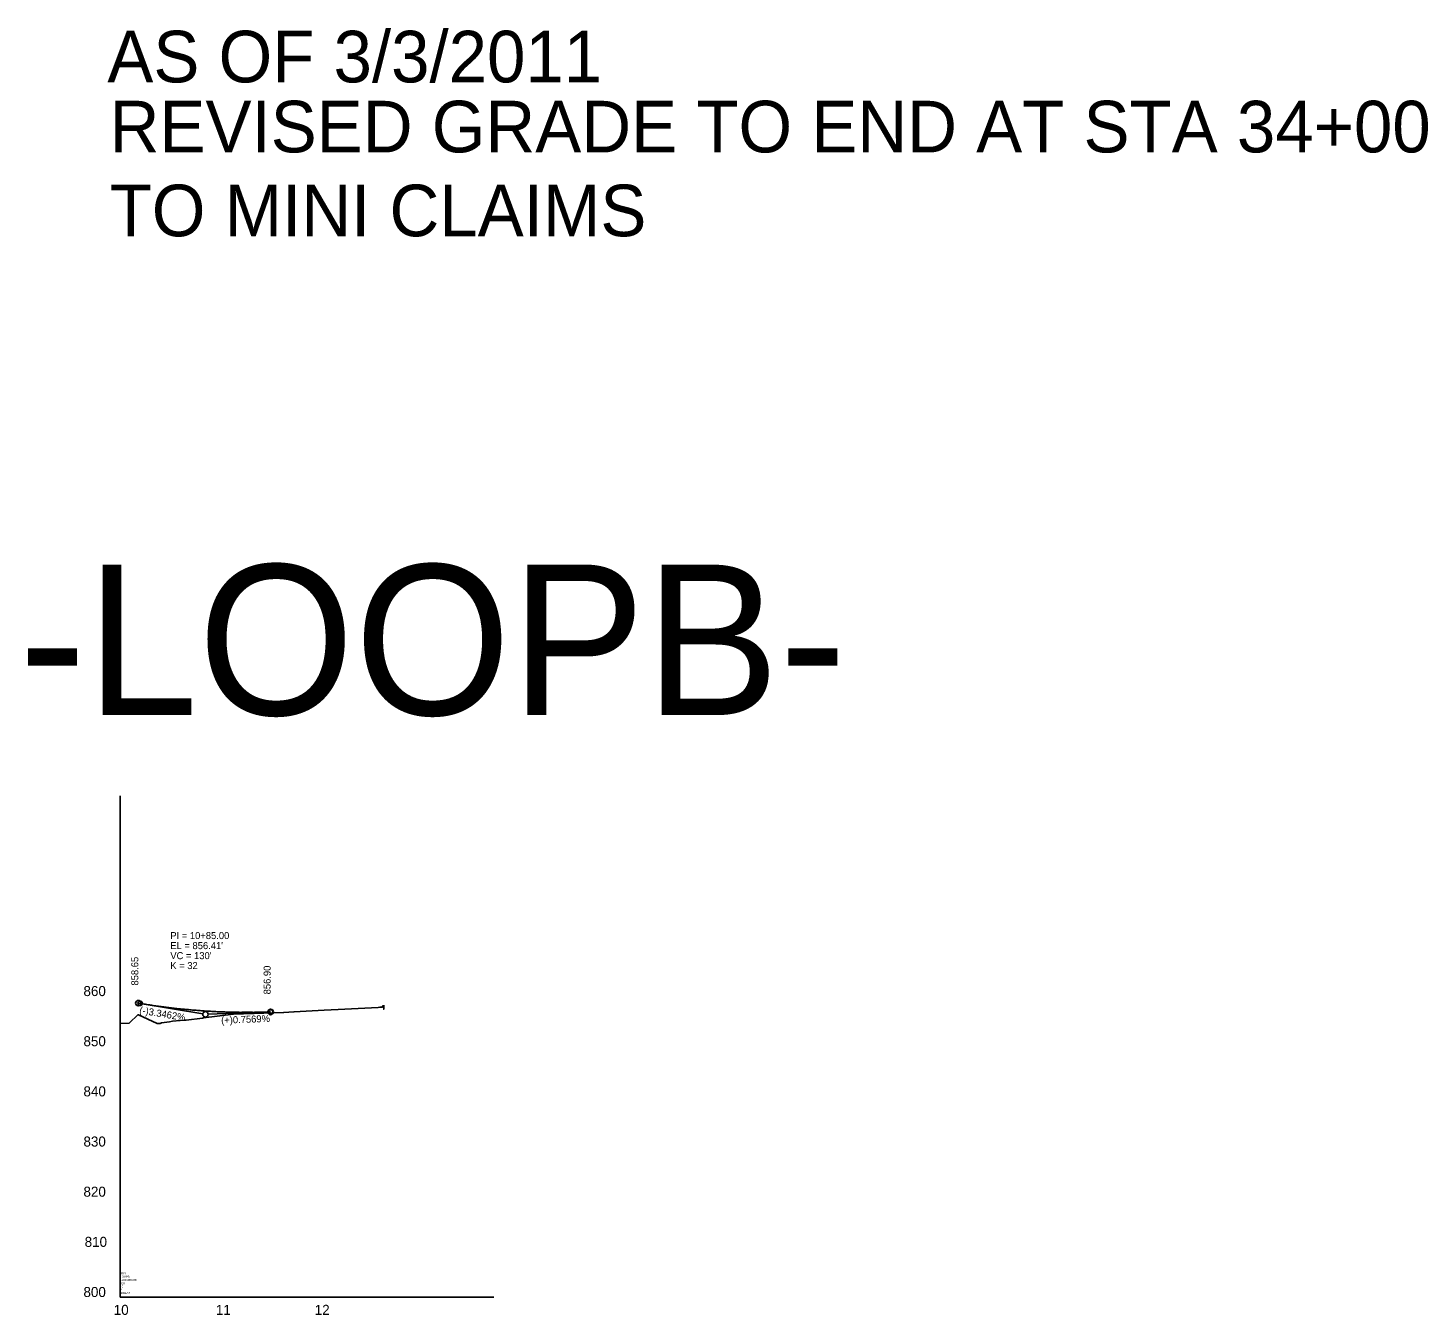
# Model space of a CAD drawing. Extents: x 570622 to 580296, y -55533 to -48575.
# Drawn here: x 573768 to 575164, y -55241 to -53958 of the extents above; entities that cross this region are included whole.
import ezdxf

# ---------------------------------------------------------------- set-up
doc = ezdxf.new("R2010")
doc.units = 0
for name, color, linetype in [('Default', 7, 'Continuous'), ('Exist Profile Cell', 7, 'Continuous'), ('Exist Vertical Profile Ground Line', 7, 'Continuous'), ('Exist Vertical Profile Horizontal Axis Label Major', 7, 'Continuous'), ('Exist Vertical Profile Vertical Axis Label', 7, 'Continuous'), ('Prop Vertical Profile Curve Label', 7, 'Continuous'), ('Prop Vertical Profile Grade', 7, 'Continuous'), ('Prop Vertical Profile Grade Label', 7, 'Continuous'), ('Prop VPI Label', 7, 'Continuous')]:
    doc.layers.add(name, color=color, linetype=linetype)

msp = doc.modelspace()

# ---------------------------------------------------------------- linework, layer by layer
at = {"layer": 'Exist Profile Cell'}
for q in [(573860.3, -54723.7), (574232.8, -55223.7), (573860.3, -55223.7)]:
    msp.add_line((573860.3, -55223.7), q, dxfattribs=at)
at = {"layer": 'Exist Vertical Profile Ground Line'}
msp.add_lwpolyline([(573860.3, -54950.9), (573869.2, -54950.5), (573878.1, -54941.8), (573878.5, -54942), (573897.2, -54950.9), (573900.2, -54950.6), (573901.5, -54950.2), (573909.4, -54949), (573912.5, -54948.4), (573920, -54947.7), (573924.5, -54947.3), (573926, -54947.3), (573942.5, -54945.3), (573943.4, -54945.2), (573973.4, -54941.6), (573993.4, -54940.8), (573993.9, -54940.8), (574023.1, -54939.7), (574023.5, -54939.7), (574033.5, -54939.1), (574033.8, -54939.1), (574063.6, -54937.4), (574077.6, -54936.7), (574117.4, -54934.7), (574119.1, -54934.6), (574120.5, -54934.5), (574120.9, -54934.5), (574121.6, -54934.4), (574122.3, -54933.1), (574122.7, -54933.9), (574123, -54934.6), (574123.1, -54936.5), (574123.3, -54932.6)], dxfattribs=at)
at = {"layer": 'Prop Vertical Profile Curve Label'}
for centre in [(573880.3, -54930.7), (574010.3, -54939.2)]:
    msp.add_circle(centre, 2.25, dxfattribs=at)
at = {"layer": 'Prop Vertical Profile Grade'}
msp.add_line((573878.4, -54930.4), (573880.3, -54930.7), dxfattribs=at)
msp.add_spline([(573880.3, -54930.7), (573882.9, -54931.2), (573885.5, -54931.6), (573888.1, -54932), (573890.7, -54932.4), (573893.3, -54932.8), (573895.9, -54933.2), (573898.5, -54933.5), (573901.1, -54933.9), (573903.7, -54934.2), (573906.3, -54934.6), (573908.9, -54934.9), (573911.5, -54935.2), (573914.1, -54935.5), (573916.7, -54935.8), (573919.3, -54936.1), (573921.9, -54936.3), (573924.5, -54936.6), (573927.1, -54936.8), (573929.7, -54937.1), (573932.3, -54937.3), (573934.9, -54937.5), (573937.5, -54937.7), (573940.1, -54937.9), (573942.7, -54938.1), (573945.3, -54938.3), (573947.9, -54938.4), (573950.5, -54938.6), (573953.1, -54938.7), (573955.7, -54938.9), (573958.3, -54939), (573960.9, -54939.1), (573963.5, -54939.2), (573966.1, -54939.3), (573968.7, -54939.4), (573971.3, -54939.4), (573973.9, -54939.5), (573976.5, -54939.5), (573979.1, -54939.6), (573981.7, -54939.6), (573984.3, -54939.6), (573986.9, -54939.6), (573989.5, -54939.6), (573992.1, -54939.6), (573994.7, -54939.6), (573997.3, -54939.5), (573999.9, -54939.5), (574002.5, -54939.4), (574005.1, -54939.3), (574007.7, -54939.3), (574010.3, -54939.2)], degree=3, dxfattribs=at)
at = {"layer": 'Prop VPI Label'}
for p, q in [((573880.3, -54930.7), (573942.6, -54941.2)), ((574010.3, -54939.2), (573948.1, -54941.5))]:
    msp.add_line(p, q, dxfattribs=at)
for centre in [(573878.4, -54930.4), (573945.3, -54941.6), (574010.3, -54939.2)]:
    msp.add_circle(centre, 2.75, dxfattribs=at)

# ---------------------------------------------------------------- texts
at = {"layer": 'Default'}
for s, height, p in [('AS OF 3/3/2011', 51.45, (573847.5, -54012.6)), ('REVISED GRADE TO END AT STA 34+00 ', 51.45, (573849.8, -54082.4)), ('TO MINI CLAIMS', 51.45, (573849.8, -54166)), ('-LOOPB-', 150, (573759.5, -54643.3))]:
    msp.add_text(s, height=height, dxfattribs=at).set_placement(p)
at = {"layer": 'Exist Profile Cell'}
for s, p in [('RDY', (573860.3, -55200.9)), ('LOOPB', (573860.3, -55204.2)), ('1000.000000', (573860.3, -55207.4)), ('800', (573860.3, -55210.7)), ('2', (573860.3, -55217.2)), ('10', (573860.3, -55213.9)), ('NOGAP', (573860.3, -55220.4))]:
    msp.add_text(s, height=2, dxfattribs=at).set_placement(p)
at = {"layer": 'Exist Vertical Profile Horizontal Axis Label Major'}
for s, p in [('10', (573853.9, -55241.2)), ('11', (573955.7, -55241.2)), ('12', (574054.3, -55241.2))]:
    msp.add_text(s, height=10, dxfattribs=at).set_placement(p)
at = {"layer": 'Exist Vertical Profile Vertical Axis Label'}
for s, p in [('860', (573823.7, -54923.4)), ('850', (573823.7, -54973.4)), ('840', (573823.7, -55023.4)), ('830', (573823.7, -55073.4)), ('820', (573823.7, -55123.4)), ('810', (573824.9, -55173.4)), ('800', (573823.7, -55223.4))]:
    msp.add_text(s, height=10, dxfattribs=at).set_placement(p)
at = {"layer": 'Prop Vertical Profile Curve Label'}
for s, p in [("VC = 130'", (573910.3, -54886.6)), ('K = 32', (573910.3, -54896.5))]:
    msp.add_text(s, height=7, dxfattribs=at).set_placement(p)
at = {"layer": 'Prop Vertical Profile Grade Label'}
for s, rotation, p in [('(-)3.3462%', 350.5018, (573879, -54940.7)), ('(+)0.7569%', 2.1673, (573961.1, -54951))]:
    msp.add_text(s, height=7, rotation=rotation, dxfattribs=at).set_placement(p)
at = {"layer": 'Prop VPI Label'}
for s, p in [('PI = 10+85.00', (573910.3, -54866.6)), ("EL = 856.41'", (573910.3, -54876.6))]:
    msp.add_text(s, height=7, dxfattribs=at).set_placement(p)
for s, p in [('858.65', (573878.4, -54912.9)), ('856.90', (574010.3, -54921.7))]:
    msp.add_text(s, height=7, rotation=90, dxfattribs=at).set_placement(p)

doc.saveas('drawing.dxf')
